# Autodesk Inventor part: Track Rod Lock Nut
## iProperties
Shininess: 77.0
Angle Display Precision: 2
Document Length Units: 11269
Document Angle Units: 11279
Document Time Units: 11290
Document Mass Units: 11283
Document Length Units Precision: 3
Document Angle Units Precision: 2
Compacted: True
Created: 2001-08
Part Number: Track Rod Lock Nut
Document SubType Name: Modeling
Designer: Martin Budgell
Density: 0.0
Volumn: 0.0
Area: 0.0
PropertySet Name: Model Information
Control State: 0
Master: False
Checked Out: False
Author: Martin Budgell
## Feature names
1. Extrusion1
2. Revolution1
3. Chamfer1
4. Hole1
5. Chamfer2
6. Extrusion2
